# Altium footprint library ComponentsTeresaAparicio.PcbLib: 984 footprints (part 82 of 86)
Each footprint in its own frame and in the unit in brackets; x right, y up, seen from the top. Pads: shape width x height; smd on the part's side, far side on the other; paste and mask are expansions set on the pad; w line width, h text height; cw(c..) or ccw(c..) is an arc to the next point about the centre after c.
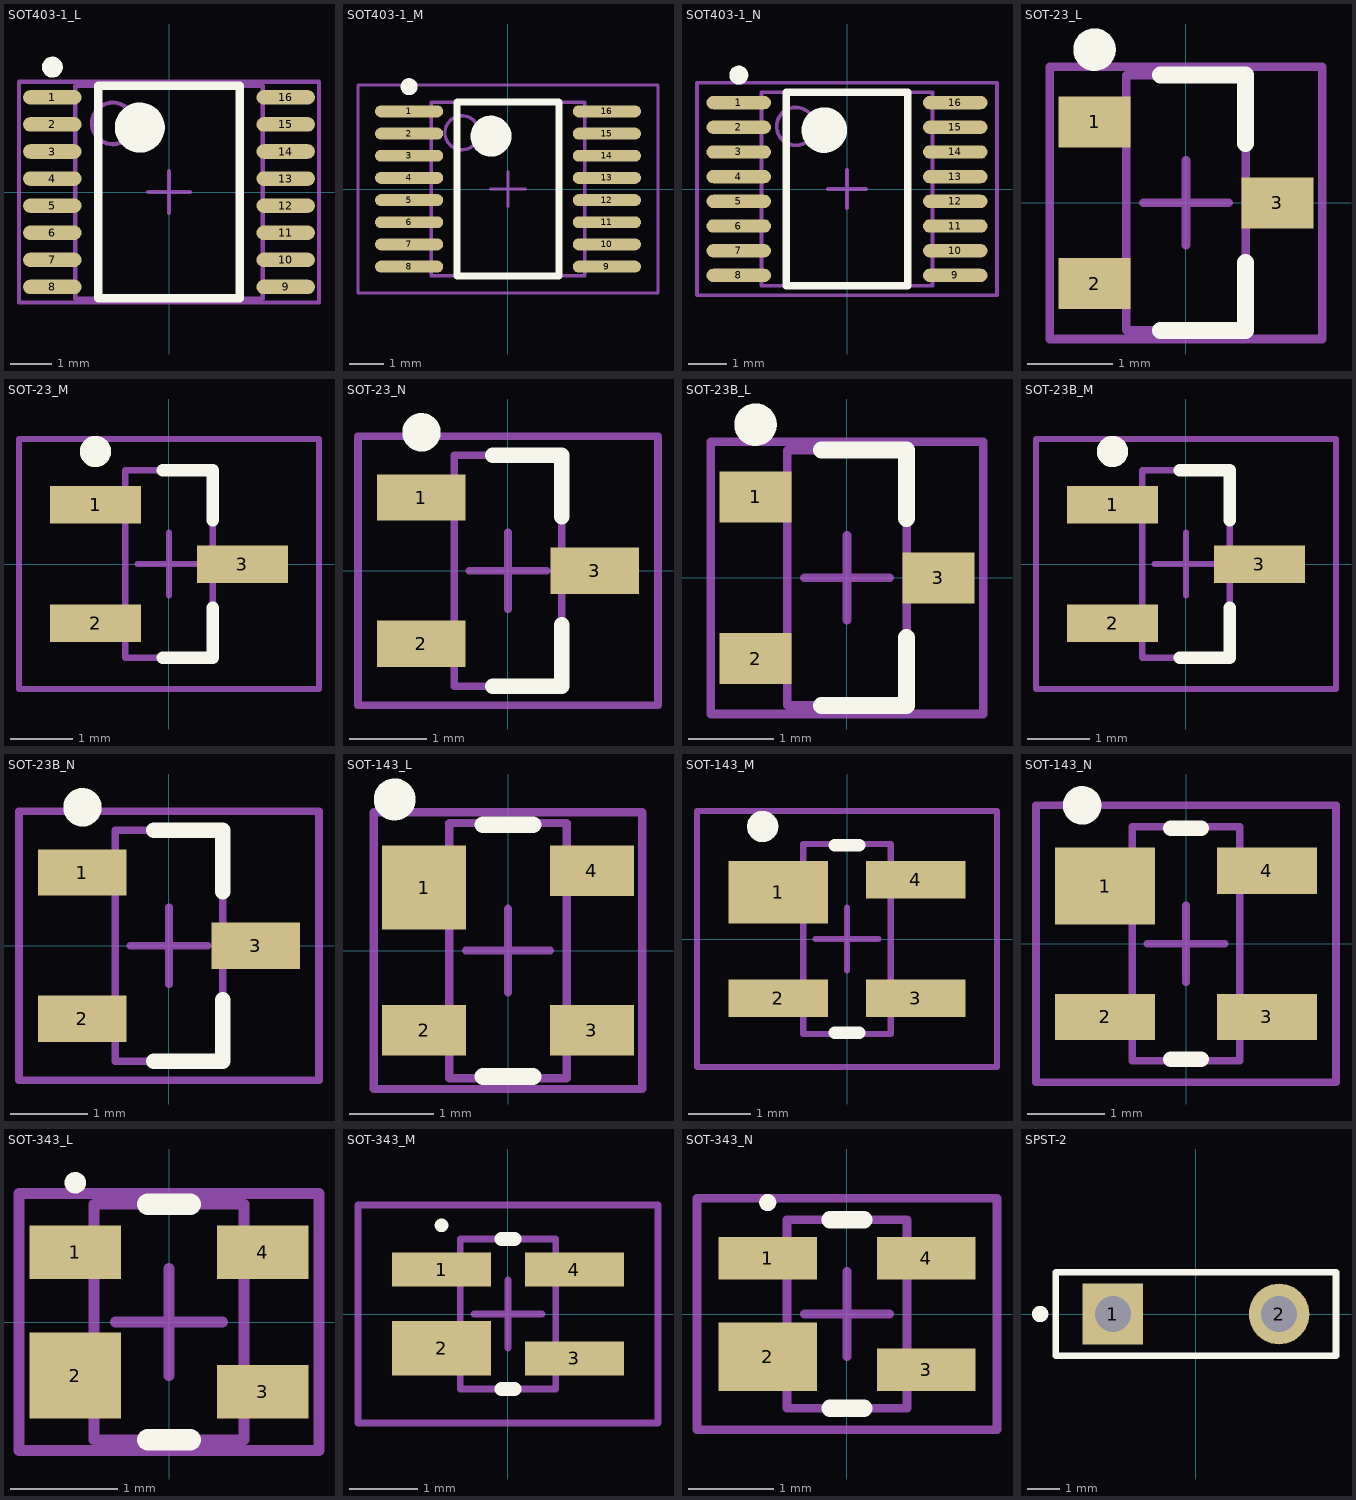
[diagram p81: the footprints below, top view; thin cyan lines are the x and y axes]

## SOT403-1_L [mm] "TSOP, 16-Leads, Body 5x4.4mm, Pitch 0.65mm, IPC High Density"
height 1.1
pads (16):
  oval 1.4x0.35 smd: 1(-2.8,2.275) 2(-2.8,1.625) 3(-2.8,0.975) 4(-2.8,0.325) 5(-2.8,-0.325) 6(-2.8,-0.975) 7(-2.8,-1.625) 8(-2.8,-2.275) 9(2.8,-2.275) 10(2.8,-1.625) 11(2.8,-0.975) 12(2.8,-0.325) 13(2.8,0.325) 14(2.8,0.975) 15(2.8,1.625) 16(2.8,2.275)
Top Overlay:
  circle w0.25: c-2.8,3 r0.125
  circle w0.6: c-0.7,1.55 r0.3
  lines w0.2: -1.7,-2.55 -1.7,2.55 1.7,2.55 1.7,-2.55 -1.7,-2.55
Mechanical 13:
  circle w0.1: c-1.35,1.65 r0.5
  lines w0.1: -2.25,-2.55 -2.25,2.55 2.25,2.55 2.25,-2.55 -2.25,-2.55
Mechanical 15:
  lines w0.1: -0.5,0 0.5,0 ; 0,-0.5 0,0.5 ; -3.6,-2.65 -3.6,2.65 3.6,2.65 3.6,-2.65 -3.6,-2.65
3D body: height 1.1, standoff 0, extent -2.25,-2.55 2.25,2.55

## SOT403-1_M [mm] "TSOP, 16-Leads, Body 5x4.4mm, Pitch 0.65mm, IPC Low Density"
height 1.1
pads (16):
  oval 2x0.35 smd: 1(-2.9,2.275) 2(-2.9,1.625) 3(-2.9,0.975) 4(-2.9,0.325) 5(-2.9,-0.325) 6(-2.9,-0.975) 7(-2.9,-1.625) 8(-2.9,-2.275) 9(2.9,-2.275) 10(2.9,-1.625) 11(2.9,-0.975) 12(2.9,-0.325) 13(2.9,0.325) 14(2.9,0.975) 15(2.9,1.625) 16(2.9,2.275)
Top Overlay:
  circle w0.25: c-2.9,3 r0.125
  circle w0.6: c-0.5,1.55 r0.3
  lines w0.2: -1.5,-2.55 -1.5,2.55 1.5,2.55 1.5,-2.55 -1.5,-2.55
Mechanical 13:
  circle w0.1: c-1.35,1.65 r0.5
  lines w0.1: -2.25,-2.55 -2.25,2.55 2.25,2.55 2.25,-2.55 -2.25,-2.55
Mechanical 15:
  lines w0.1: -0.5,0 0.5,0 ; 0,-0.5 0,0.5 ; -4.4,-3.05 -4.4,3.05 4.4,3.05 4.4,-3.05 -4.4,-3.05
3D body: height 1.1, standoff 0, extent -2.25,-2.55 2.25,2.55

## SOT403-1_N [mm] "TSOP, 16-Leads, Body 5x4.4mm, Pitch 0.65mm, IPC Medium Density"
height 1.1
pads (16):
  oval 1.7x0.35 smd: 1(-2.85,2.275) 2(-2.85,1.625) 3(-2.85,0.975) 4(-2.85,0.325) 5(-2.85,-0.325) 6(-2.85,-0.975) 7(-2.85,-1.625) 8(-2.85,-2.275) 9(2.85,-2.275) 10(2.85,-1.625) 11(2.85,-0.975) 12(2.85,-0.325) 13(2.85,0.325) 14(2.85,0.975) 15(2.85,1.625) 16(2.85,2.275)
Top Overlay:
  circle w0.25: c-2.85,3 r0.125
  circle w0.6: c-0.6,1.55 r0.3
  lines w0.2: -1.6,-2.55 -1.6,2.55 1.6,2.55 1.6,-2.55 -1.6,-2.55
Mechanical 13:
  circle w0.1: c-1.35,1.65 r0.5
  lines w0.1: -2.25,-2.55 -2.25,2.55 2.25,2.55 2.25,-2.55 -2.25,-2.55
Mechanical 15:
  lines w0.1: -0.5,0 0.5,0 ; 0,-0.5 0,0.5 ; -3.95,-2.8 -3.95,2.8 3.95,2.8 3.95,-2.8 -3.95,-2.8
3D body: height 1.1, standoff 0, extent -2.25,-2.55 2.25,2.55

## SOT-23_L [mm] "SOT23, 3-Leads, Body 2.9x1.3mm, Pitch 0.95mm, Lead Span 2.5mm, IPC High Density"
height 1.1
pads (3):
  rect 0.85x0.6 smd: 1(-1.075,0.95) 2(-1.075,-0.95) 3(1.075,0)
Top Overlay:
  circle w0.25: c-1.075,1.8 r0.125
  lines w0.2: -0.3,-1.5 0.7,-1.5 0.7,-0.7 ; -0.3,1.5 0.7,1.5 0.7,0.7
Mechanical 13:
  lines w0.1: -0.7,-1.5 -0.7,1.5 0.7,1.5 0.7,-1.5 -0.7,-1.5
Mechanical 15:
  lines w0.1: -0.5,0 0.5,0 ; 0,-0.5 0,0.5 ; -1.6,-1.6 -1.6,1.6 1.6,1.6 1.6,-1.6 -1.6,-1.6
3D body: height 1.1, standoff 0, extent -0.7,-1.5 0.7,1.5

## SOT-23_M [mm] "SOT23, 3-Leads, Body 2.9x1.3mm, Pitch 0.95mm, Lead Span 2.5mm, IPC Low Density"
height 1.1
pads (3):
  rect 1.45x0.6 smd: 1(-1.175,0.95) 2(-1.175,-0.95) 3(1.175,0)
Top Overlay:
  circle w0.25: c-1.175,1.8 r0.125
  lines w0.2: -0.1,-1.5 0.7,-1.5 0.7,-0.7 ; -0.1,1.5 0.7,1.5 0.7,0.7
Mechanical 13:
  lines w0.1: -0.7,-1.5 -0.7,1.5 0.7,1.5 0.7,-1.5 -0.7,-1.5
Mechanical 15:
  lines w0.1: -0.5,0 0.5,0 ; 0,-0.5 0,0.5 ; -2.4,-2 -2.4,2 2.4,2 2.4,-2 -2.4,-2
3D body: height 1.1, standoff 0, extent -0.7,-1.5 0.7,1.5

## SOT-23_N [mm] "SOT23, 3-Leads, Body 2.9x1.3mm, Pitch 0.95mm, Lead Span 2.5mm, IPC Medium Density"
height 1.1
pads (3):
  rect 1.15x0.6 smd: 1(-1.125,0.95) 2(-1.125,-0.95) 3(1.125,0)
Top Overlay:
  circle w0.25: c-1.125,1.8 r0.125
  lines w0.2: -0.2,-1.5 0.7,-1.5 0.7,-0.7 ; -0.2,1.5 0.7,1.5 0.7,0.7
Mechanical 13:
  lines w0.1: -0.7,-1.5 0.7,-1.5 0.7,1.5 -0.7,1.5 -0.7,-1.5
Mechanical 15:
  lines w0.1: -0.5,0 0.5,0 ; 0,-0.5 0,0.5 ; -1.95,-1.75 1.95,-1.75 1.95,1.75 -1.95,1.75 -1.95,-1.75
3D body: height 1.1, standoff 0, extent -0.7,-1.5 0.7,1.5

## SOT-23B_L [mm] "SOT23, 3-Leads, Body 2.9x1.3mm, Pitch 0.95mm, Lead Span 2.4mm, IPC High Density"
height 1.14
pads (3):
  rect 0.85x0.6 smd: 1(-1.075,0.95) 2(-1.075,-0.95) 3(1.075,0)
Top Overlay:
  circle w0.25: c-1.075,1.8 r0.125
  lines w0.2: -0.3,-1.5 0.7,-1.5 0.7,-0.7 ; -0.3,1.5 0.7,1.5 0.7,0.7
Mechanical 13:
  lines w0.1: -0.7,-1.5 0.7,-1.5 0.7,1.5 -0.7,1.5 -0.7,-1.5
Mechanical 15:
  lines w0.1: -0.5,0 0.5,0 ; 0,-0.5 0,0.5 ; -1.6,-1.6 1.6,-1.6 1.6,1.6 -1.6,1.6 -1.6,-1.6
3D body: height 1.14, standoff 0, extent -0.7,-1.5 0.7,1.5

## SOT-23B_M [mm] "SOT23, 3-Leads, Body 2.9x1.3mm, Pitch 0.95mm, Lead Span 2.4mm, IPC Low Density"
height 1.14
pads (3):
  rect 1.45x0.6 smd: 1(-1.175,0.95) 2(-1.175,-0.95) 3(1.175,0)
Top Overlay:
  circle w0.25: c-1.175,1.8 r0.125
  lines w0.2: -0.1,-1.5 0.7,-1.5 0.7,-0.7 ; -0.1,1.5 0.7,1.5 0.7,0.7
Mechanical 13:
  lines w0.1: -0.7,-1.5 0.7,-1.5 0.7,1.5 -0.7,1.5 -0.7,-1.5
Mechanical 15:
  lines w0.1: -0.5,0 0.5,0 ; 0,-0.5 0,0.5 ; -2.4,-2 2.4,-2 2.4,2 -2.4,2 -2.4,-2
3D body: height 1.14, standoff 0, extent -0.7,-1.5 0.7,1.5

## SOT-23B_N [mm] "SOT23, 3-Leads, Body 2.9x1.3mm, Pitch 0.95mm, Lead Span 2.4mm, IPC Medium Density"
height 1.14
pads (3):
  rect 1.15x0.6 smd: 1(-1.125,0.95) 2(-1.125,-0.95) 3(1.125,0)
Top Overlay:
  circle w0.25: c-1.125,1.8 r0.125
  lines w0.2: -0.2,-1.5 0.7,-1.5 0.7,-0.7 ; -0.2,1.5 0.7,1.5 0.7,0.7
Mechanical 13:
  lines w0.1: -0.7,-1.5 0.7,-1.5 0.7,1.5 -0.7,1.5 -0.7,-1.5
Mechanical 15:
  lines w0.1: -0.5,0 0.5,0 ; 0,-0.5 0,0.5 ; -1.95,-1.75 1.95,-1.75 1.95,1.75 -1.95,1.75 -1.95,-1.75
3D body: height 1.14, standoff 0, extent -0.7,-1.5 0.7,1.5

## SOT-143_L [mm] "SOT143, 4-Leads, Body 2.9x1.3mm, Pitch 1.9mm, Lead Span 2.5mm, IPC High Density"
height 1.1
pads (4):
  rect 1x1 smd: 1(-1,0.75)
  rect 1x0.6 smd: 2(-1,-0.95) 3(1,-0.95) 4(1,0.95)
Top Overlay:
  circle w0.25: c-1.35,1.8 r0.125
  lines w0.2: -0.3,-1.5 0.3,-1.5 ; -0.3,1.5 0.3,1.5
Mechanical 13:
  lines w0.1: -0.7,-1.52 0.7,-1.52 0.7,1.52 -0.7,1.52 -0.7,-1.52
Mechanical 15:
  lines w0.1: -0.5,0 0.5,0 ; 0,-0.5 0,0.5 ; -1.6,-1.65 1.6,-1.65 1.6,1.65 -1.6,1.65 -1.6,-1.65
3D body: height 1.1, standoff 0, extent -0.7,-1.52 0.7,1.52

## SOT-143_M [mm] "SOT143, 4-Leads, Body 2.9x1.3mm, Pitch 1.9mm, Lead Span 2.5mm, IPC Low Density"
height 1.1
pads (4):
  rect 1.6x1 smd: 1(-1.1,0.75)
  rect 1.6x0.6 smd: 2(-1.1,-0.95) 3(1.1,-0.95) 4(1.1,0.95)
Top Overlay:
  circle w0.25: c-1.35,1.8 r0.125
  lines w0.2: -0.2,-1.5 0.2,-1.5 ; -0.2,1.5 0.2,1.5
Mechanical 13:
  lines w0.1: -0.7,-1.52 -0.7,1.52 0.7,1.52 0.7,-1.52 -0.7,-1.52
Mechanical 15:
  lines w0.1: -0.5,0 0.5,0 ; 0,-0.5 0,0.5 ; -2.4,-2.05 -2.4,2.05 2.4,2.05 2.4,-2.05 -2.4,-2.05
3D body: height 1.1, standoff 0, extent -0.7,-1.52 0.7,1.52

## SOT-143_N [mm] "SOT143, 4-Leads, Body 2.9x1.3mm, Pitch 1.9mm, Lead Span 2.5mm, IPC Medium Density"
height 1.1
pads (4):
  rect 1.3x1 smd: 1(-1.05,0.75)
  rect 1.3x0.6 smd: 2(-1.05,-0.95) 3(1.05,-0.95) 4(1.05,0.95)
Top Overlay:
  circle w0.25: c-1.35,1.8 r0.125
  lines w0.2: -0.2,-1.5 0.2,-1.5 ; -0.2,1.5 0.2,1.5
Mechanical 13:
  lines w0.1: -0.7,-1.52 -0.7,1.52 0.7,1.52 0.7,-1.52 -0.7,-1.52
Mechanical 15:
  lines w0.1: -0.5,0 0.5,0 ; 0,-0.5 0,0.5 ; -1.95,-1.8 -1.95,1.8 1.95,1.8 1.95,-1.8 -1.95,-1.8
3D body: height 1.1, standoff 0, extent -0.7,-1.52 0.7,1.52

## SOT-343_L [mm] "SOT343, 4-Leads, Body 2x1.3 mm, Pitch 1.3mm, Lead Span 2.1mm, IPC High Density"
height 1
pads (4):
  rect 0.85x0.5 smd: 1(-0.875,0.65) 3(0.875,-0.65) 4(0.875,0.65)
  rect 0.85x0.8 smd: 2(-0.875,-0.5)
Top Overlay:
  circle w0.1: c-0.875,1.3 r0.05
  lines w0.2: -0.2,-1.1 0.2,-1.1 ; -0.2,1.1 0.2,1.1
Mechanical 13:
  lines w0.1: -0.7,-1.1 -0.7,1.1 0.7,1.1 0.7,-1.1 -0.7,-1.1
Mechanical 15:
  lines w0.1: -0.5,0 0.5,0 ; 0,-0.5 0,0.5 ; -1.4,-1.2 -1.4,1.2 1.4,1.2 1.4,-1.2 -1.4,-1.2
3D body: height 1, standoff 0, extent -0.7,-1.1 0.7,1.1

## SOT-343_M [mm] "SOT343, 4-Leads, Body 2x1.3 mm, Pitch 1.3mm, Lead Span 2.1mm, IPC Low Density"
height 1
pads (4):
  rect 1.45x0.5 smd: 1(-0.975,0.65) 3(0.975,-0.65) 4(0.975,0.65)
  rect 1.45x0.8 smd: 2(-0.975,-0.5)
Top Overlay:
  circle w0.1: c-0.975,1.3 r0.05
  lines w0.2: -0.1,-1.1 0.1,-1.1 ; -0.1,1.1 0.1,1.1
Mechanical 13:
  lines w0.1: -0.7,-1.1 0.7,-1.1 0.7,1.1 -0.7,1.1 -0.7,-1.1
Mechanical 15:
  lines w0.1: -0.5,0 0.5,0 ; 0,-0.5 0,0.5 ; -2.2,-1.6 2.2,-1.6 2.2,1.6 -2.2,1.6 -2.2,-1.6
3D body: height 1, standoff 0, extent -0.7,-1.1 0.7,1.1

## SOT-343_N [mm] "SOT343, 4-Leads, Body 2x1.3 mm, Pitch 1.3mm, Lead Span 2.1mm, IPC Medium Density"
height 1
pads (4):
  rect 1.15x0.5 smd: 1(-0.925,0.65) 3(0.925,-0.65) 4(0.925,0.65)
  rect 1.15x0.8 smd: 2(-0.925,-0.5)
Top Overlay:
  circle w0.1: c-0.925,1.3 r0.05
  lines w0.2: -0.2,-1.1 0.2,-1.1 ; -0.2,1.1 0.2,1.1
Mechanical 13:
  lines w0.1: -0.7,-1.1 0.7,-1.1 0.7,1.1 -0.7,1.1 -0.7,-1.1
Mechanical 15:
  lines w0.1: -0.5,0 0.5,0 ; 0,-0.5 0,0.5 ; -1.75,-1.35 1.75,-1.35 1.75,1.35 -1.75,1.35 -1.75,-1.35
3D body: height 1, standoff 0, extent -0.7,-1.1 0.7,1.1

## SPST-2 [mm] "Switch; 2 Leads"
pads (2):
  rect 1.85x1.85 hole 1.1: 1(-2.54,0)
  round 1.85 hole 1.1: 2(2.54,0)
Top Overlay:
  circle w0.25: c-4.761,-0.001 r0.125
  lines w0.2: -4.28,-1.27 4.28,-1.27 4.28,1.27 -4.28,1.27 -4.28,-1.27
